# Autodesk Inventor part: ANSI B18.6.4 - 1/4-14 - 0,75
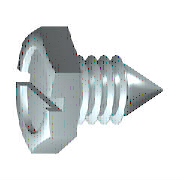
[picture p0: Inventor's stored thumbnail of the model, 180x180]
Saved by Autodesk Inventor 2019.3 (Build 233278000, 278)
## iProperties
Created: 2018-01
Part Number: ANSI B18.6.4 - 1/4-14 - 0,75
Material: Ocel, měkká
Description: Šroub do plechu s normální vroubkovanou šestihrannou hlavou - Typ BP - Palcový
Document SubType Name: Modeling
Standard: ANSI B18.6.4
Designer: B-hon
Standard Revision: 1998
Standards Organization: ANSI
Language: cs-CZ
Size Designation: 1/4-14 - 0,75
Categories: <MemberInstance><Categories><Category DisplayName="Spojovací materiál" InternalName="e4da775c-781d-43d5-af7c-5136215cf5a6" Mnemonic="FSTN"><Category DisplayName
Density: 7.85 g/cm^3
Appearance: Pololeštěná
IsCustomPart: 0
Author: B-hon
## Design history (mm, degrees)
sketch "Náčrt1"
  geometry: L1 (0, 3.175)-(0, 0); L2 (0, 0)-(19.05, 0); L3 (19.05, 0)-(19.05, 3.175); L4 (19.05, 3.175)-(0, 3.175); L5 (-3.81, 0)-(22.86, 0) reference; L6 (0, -0.635)-(0, 3.81) reference
  constraints: 8 end point, 2 collinear, 2 parallel, 1 perpendicular, 1 point on line, 1 vertical
  dimensions: "d0" = 6.35 diameter of L4 L2 (= NND); "d1" = 19.05 distance between parallel lines of L3 L1 (= NLG)
revolve "Těleso" sketch "Náčrt1" stored, may be unused: angle "d5" = 90 deg
sketch "Náčrt2"
  geometry: L1 (0, 5.499)-(4.763, 2.75); L2 (4.763, 2.75)-(4.763, -2.75); L3 (4.763, -2.75)-(0, -5.499); L4 (0, -5.499)-(-4.763, -2.75); L5 (-4.763, -2.75)-(-4.763, 2.75); L6 (-4.763, 2.75)-(0, 5.499); C1 r 3.175 at (0, 0) reference; 1 further point
  constraints: 12 end point, 1 coincident, 1 vertical, 11 other
  dimensions: "d2" = 9.525 distance between parallel lines of L2 L5 (= SW)
extrude "Hlava" join sketch "Náčrt2" distance "d3" = 4.826 (= KOH); taper "d4" = 0 deg
sketch "Náčrt3"
  geometry: C1 r 3.81 at (0, 0); 1 further point
  constraints: 1 centre point, 1 coincident
  dimensions: "d8" = 7.62 diameter of C1 (= SD3)
extrude "Zářez1" cut sketch "Náčrt3" distance "d9" = 0.4827 (computed from SB); taper "d10" = 0 deg
sketch "Náčrt4"
  geometry: L1 (0, 5.499)-(0, 2.75) reference; L2 (-8.464, 0)-(3.638, 0) reference; L3 (0, 5.499)-(-4.826, 5.499) reference; L4 (-4.826, 5.499)-(-4.826, 2.75) reference; L5 (-4.826, 5.499)-(-4.239, 5.499); L6 (-4.826, 5.499)-(-4.826, 4.762); L7 (-2.413, 5.499)-(-2.413, 0); L8 (0, 5.499)-(-0.587, 5.499); L9 (0, 5.499)-(0, 4.763); A1 r 8.249 centre (1.909, 0) between (-4.239, 5.499) and (-4.826, 4.762); A2 r 8.249 centre (-6.735, 0) between (0, 4.763) and (-0.587, 5.499)
  constraints: 10 end point, 4 point on circle, 3 point on line, 3 symmetric about line, 2 centre point, 2 midpoint, 1 parallel, 3 other
  dimensions: "d12" = 8.24889 radius of A1 (= 0.866025 x SW); "d14" = 9.525 diameter of L6.end L2 (= SW)
revolve "Zkosení1" sketch "Náčrt4" stored, may be unused: angle "d13" = 90 deg
sketch "Náčrt5"
  geometry: L1 (0, -7.699)-(0, 7.699) reference; L2 (-6.668, 0)-(6.668, 0) reference; L3 (-4.763, 0.953)-(4.763, 0.953); L4 (4.763, 0.953)-(4.763, -0.952); L5 (4.763, -0.952)-(-4.763, -0.952); L6 (-4.763, -0.952)-(-4.763, 0.953); L7 (-4.763, 0)-(4.763, 0); L8 (-2.388, 0)-(-4.763, 2.75) reference; L9 (4.763, 2.75)-(2.388, 0) reference
  constraints: 10 end point, 3 collinear, 2 midpoint, 2 parallel, 1 horizontal, 1 perpendicular
  dimensions: "d16" = 1.905 distance of L3.end L4.end (= SBR)
extrude "Drážka" cut sketch "Náčrt5" distance "d17" = 2.5654 (= STI); taper "d18" = 0 deg
workplane "Work Plane1"
body "Solid1"
feature "Závit" dims "d6" = 19.05 (= GEL), "d7" = 0
chamfer "Zkosení2" distance "d19" = 3.1623 (= -0.5 x GD2 + 0.5 x NND); stored, may be unused: second distance "d20" = 8.72319 (= SPTZ), angle "d37" = 45 deg
other parameters: "NLG" = 19.05 [user parameter; used in 1 equation term], "KOH" = 4.826 [user parameter; used in 2 equation terms], "NND" = 6.35 [user parameter; used in 2 equation terms], "GEL" = 19.05 [user parameter; used in 1 equation term], "SW" = 9.525 [user parameter; used in 4 equation terms], "SD3" = 7.62 (= 0.8 x SW) [user parameter; used in 1 equation term], "SB" = 0.4826 (= 0.1 x KOH) [user parameter; used in 1 equation term], "GD2" = 0.0254 [user parameter; used in 1 equation term], "d15" = 0, "STI" = 2.5654 [user parameter; used in 1 equation term], "SBR" = 1.905 [user parameter; used in 1 equation term], "SPTZ" = 8.72319 [user parameter; used in 1 equation term], "d38" = 0, "d39" = 0, "GD1" = 4.8768 [user parameter], "THREADDIA" = 6.35 [user parameter], "TOA" = 4.81362 [user parameter], "PTC" = 1.81429 (computed from TPU) [user parameter], "E0" = 10.3886 [user parameter]
